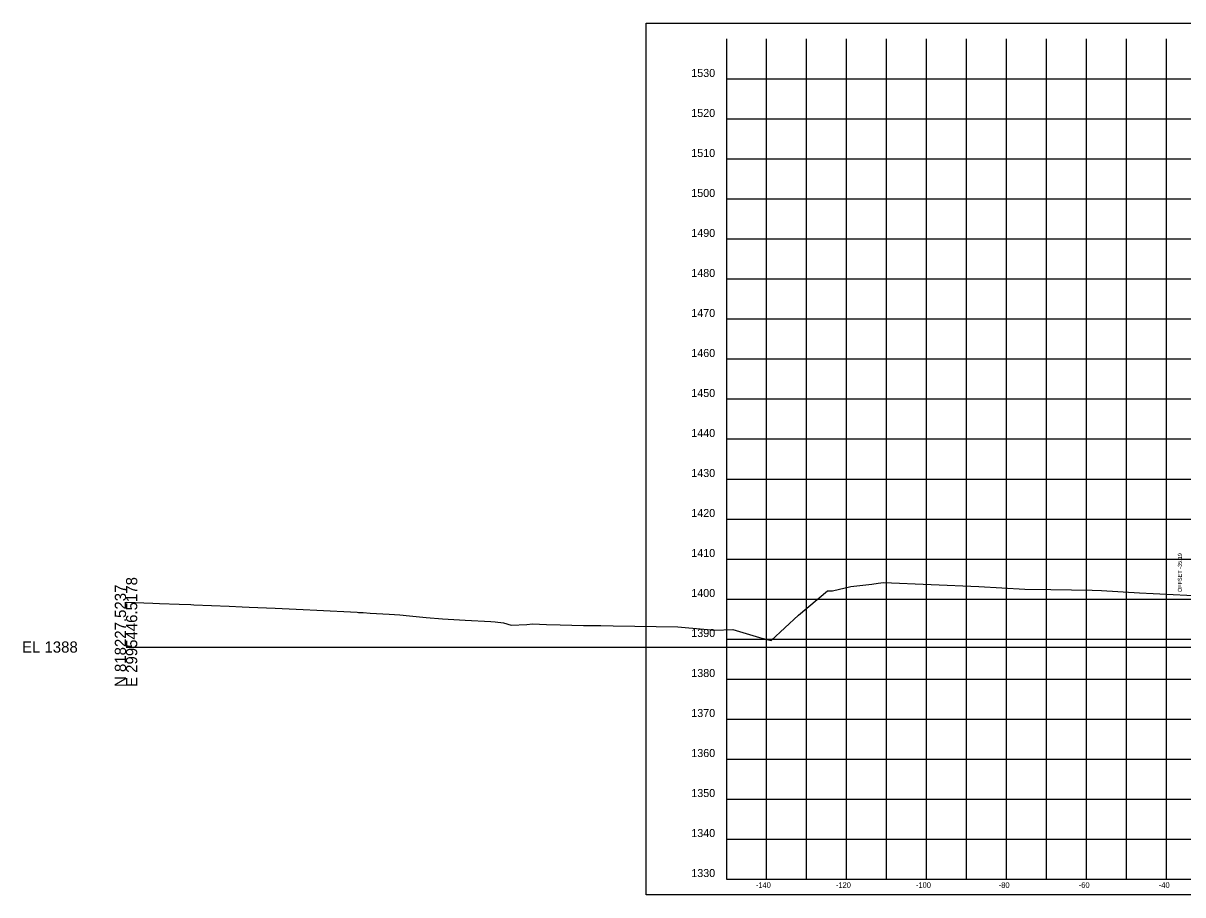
# Model space of a CAD drawing. Extents: x -26 to 603, y -10 to 2564.
# Drawn here: x -25.7 to 264.1, y 1438.1 to 1655.9 of the extents above; entities that cross this region are included whole.
import ezdxf

# ---------------------------------------------------------------- set-up
doc = ezdxf.new("R2010")
doc.units = 0
for name, color, linetype in [('DESIGN - SHEET - Corner Text', 7, 'Continuous'), ('DESIGN - SHEET - Light Grid', 7, 'Continuous'), ('DESIGN - SHEET - Linework', 7, 'Continuous'), ('DESIGN - SHEET - Plot Shape', 7, 'Continuous'), ('DESIGN - TYPICAL - Slope Tie Text', 7, 'Continuous'), ('SURVEY - GROUND - Top of Ground', 7, 'Continuous')]:
    doc.layers.add(name, color=color, linetype=linetype)

msp = doc.modelspace()

# ---------------------------------------------------------------- linework, layer by layer
at = {"layer": 'DESIGN - SHEET - Light Grid'}
msp.add_line((0, 1500), (300, 1500), dxfattribs=at)
at = {"layer": 'DESIGN - SHEET - Linework'}
for p, q in [((160, 1442), (160, 1652)), ((170, 1442), (170, 1652)), ((180, 1442), (180, 1652)), ((190, 1442), (190, 1652)), ((200, 1442), (200, 1652)), ((210, 1442), (210, 1652)), ((220, 1442), (220, 1652)), ((230, 1442), (230, 1652)), ((240, 1442), (240, 1652)), ((250, 1442), (250, 1652)), ((260, 1442), (260, 1652)), ((150, 1642), (450, 1642)), ((150, 1632), (450, 1632)), ((150, 1622), (450, 1622)), ((150, 1612), (450, 1612)), ((150, 1602), (450, 1602)), ((150, 1592), (450, 1592)), ((150, 1582), (450, 1582)), ((150, 1572), (450, 1572)), ((150, 1562), (450, 1562)), ((150, 1552), (450, 1552)), ((150, 1542), (450, 1542)), ((150, 1532), (450, 1532)), ((150, 1522), (450, 1522)), ((150, 1512), (450, 1512)), ((150, 1502), (450, 1502)), ((150, 1492), (450, 1492)), ((150, 1482), (450, 1482)), ((150, 1472), (450, 1472)), ((150, 1462), (450, 1462)), ((150, 1452), (450, 1452))]:
    msp.add_line(p, q, dxfattribs=at)
msp.add_lwpolyline([(150, 1652), (150, 1442), (450, 1442), (450, 1652)], dxfattribs=at)
at = {"layer": 'DESIGN - SHEET - Plot Shape'}
msp.add_lwpolyline([(130, 1655.94), (470, 1655.94), (470, 1438.06), (130, 1438.06)], close=True, dxfattribs=at)
at = {"layer": 'SURVEY - GROUND - Top of Ground'}
msp.add_lwpolyline([(0, 1511.25), (6.69, 1510.98), (8.36, 1510.92), (13.32, 1510.72), (16.2, 1510.61), (16.93, 1510.57), (25.77, 1510.23), (29, 1510.07), (30.78, 1509.98), (37.29, 1509.71), (44.24, 1509.36), (47.69, 1509.21), (57.72, 1508.69), (58.07, 1508.67), (59.25, 1508.61), (61.04, 1508.5), (65.74, 1508.22), (68.4, 1508.08), (70.79, 1507.77), (75.01, 1507.4), (79.09, 1507.04), (84.78, 1506.7), (91.18, 1506.36), (92.26, 1506.29), (94.28, 1506.06), (96.24, 1505.49), (100.17, 1505.6), (101.57, 1505.81), (105.08, 1505.63), (108.45, 1505.54), (114.34, 1505.39), (118.6, 1505.41), (121.72, 1505.33), (137.89, 1505.02), (144.37, 1504.44), (146.19, 1504.26), (147.02, 1504.24), (151.6, 1504.38), (158.3, 1502.4), (161.17, 1501.65), (168.06, 1507.97), (175.27, 1514.07), (176.53, 1514.01), (181.12, 1515.09), (186.39, 1515.7), (187.95, 1516), (189.25, 1516.09), (213.05, 1515.12), (224.62, 1514.5), (231.07, 1514.37), (241.38, 1514.2), (243.74, 1514.11), (253.21, 1513.51), (256.65, 1513.34), (270.04, 1512.72)], dxfattribs=at)

# ---------------------------------------------------------------- texts
at = {"layer": 'DESIGN - SHEET - Corner Text'}
for s, height, p in [('1530', 2, (141.25, 1642.5)), ('1520', 2, (141.25, 1632.5)), ('1510', 2, (141.25, 1622.5)), ('1500', 2, (141.25, 1612.5)), ('1490', 2, (141.25, 1602.5)), ('1480', 2, (141.25, 1592.5)), ('1470', 2, (141.25, 1582.5)), ('1460', 2, (141.25, 1572.5)), ('1450', 2, (141.25, 1562.5)), ('1440', 2, (141.25, 1552.5)), ('1430', 2, (141.25, 1542.5)), ('1420', 2, (141.25, 1532.5)), ('1410', 2, (141.25, 1522.5)), ('1400', 2, (141.25, 1512.5)), ('1390', 2, (141.25, 1502.5)), ('1380', 2, (141.25, 1492.5)), ('1370', 2, (141.25, 1482.5)), ('1360', 2, (141.25, 1472.5)), ('1350', 2, (141.25, 1462.5)), ('1340', 2, (141.25, 1452.5)), ('1330', 2, (141.25, 1442.5)), ('-140', 1.4, (157.37, 1439.8)), ('-120', 1.4, (177.37, 1439.8)), ('-100', 1.4, (197.37, 1439.8)), ('-80', 1.4, (218.06, 1439.8)), ('-60', 1.4, (238.06, 1439.8)), ('-40', 1.4, (258.06, 1439.8))]:
    msp.add_text(s, height=height, dxfattribs=at).set_placement(p)
at = {"layer": 'DESIGN - SHEET - Light Grid'}
for s, p in [('N 818227.5237', (0, 1490)), ('E 2995446.5178', (2.8, 1490))]:
    msp.add_text(s, height=2.8, rotation=90, dxfattribs=at).set_placement(p)
msp.add_text('EL 1388', height=2.8, dxfattribs=at).set_placement((-26, 1498.6))
at = {"layer": 'DESIGN - TYPICAL - Slope Tie Text'}
msp.add_text('OFFSET -35.19', height=1, rotation=90, dxfattribs=at).set_placement((263.81, 1513.72))

doc.saveas('drawing.dxf')
